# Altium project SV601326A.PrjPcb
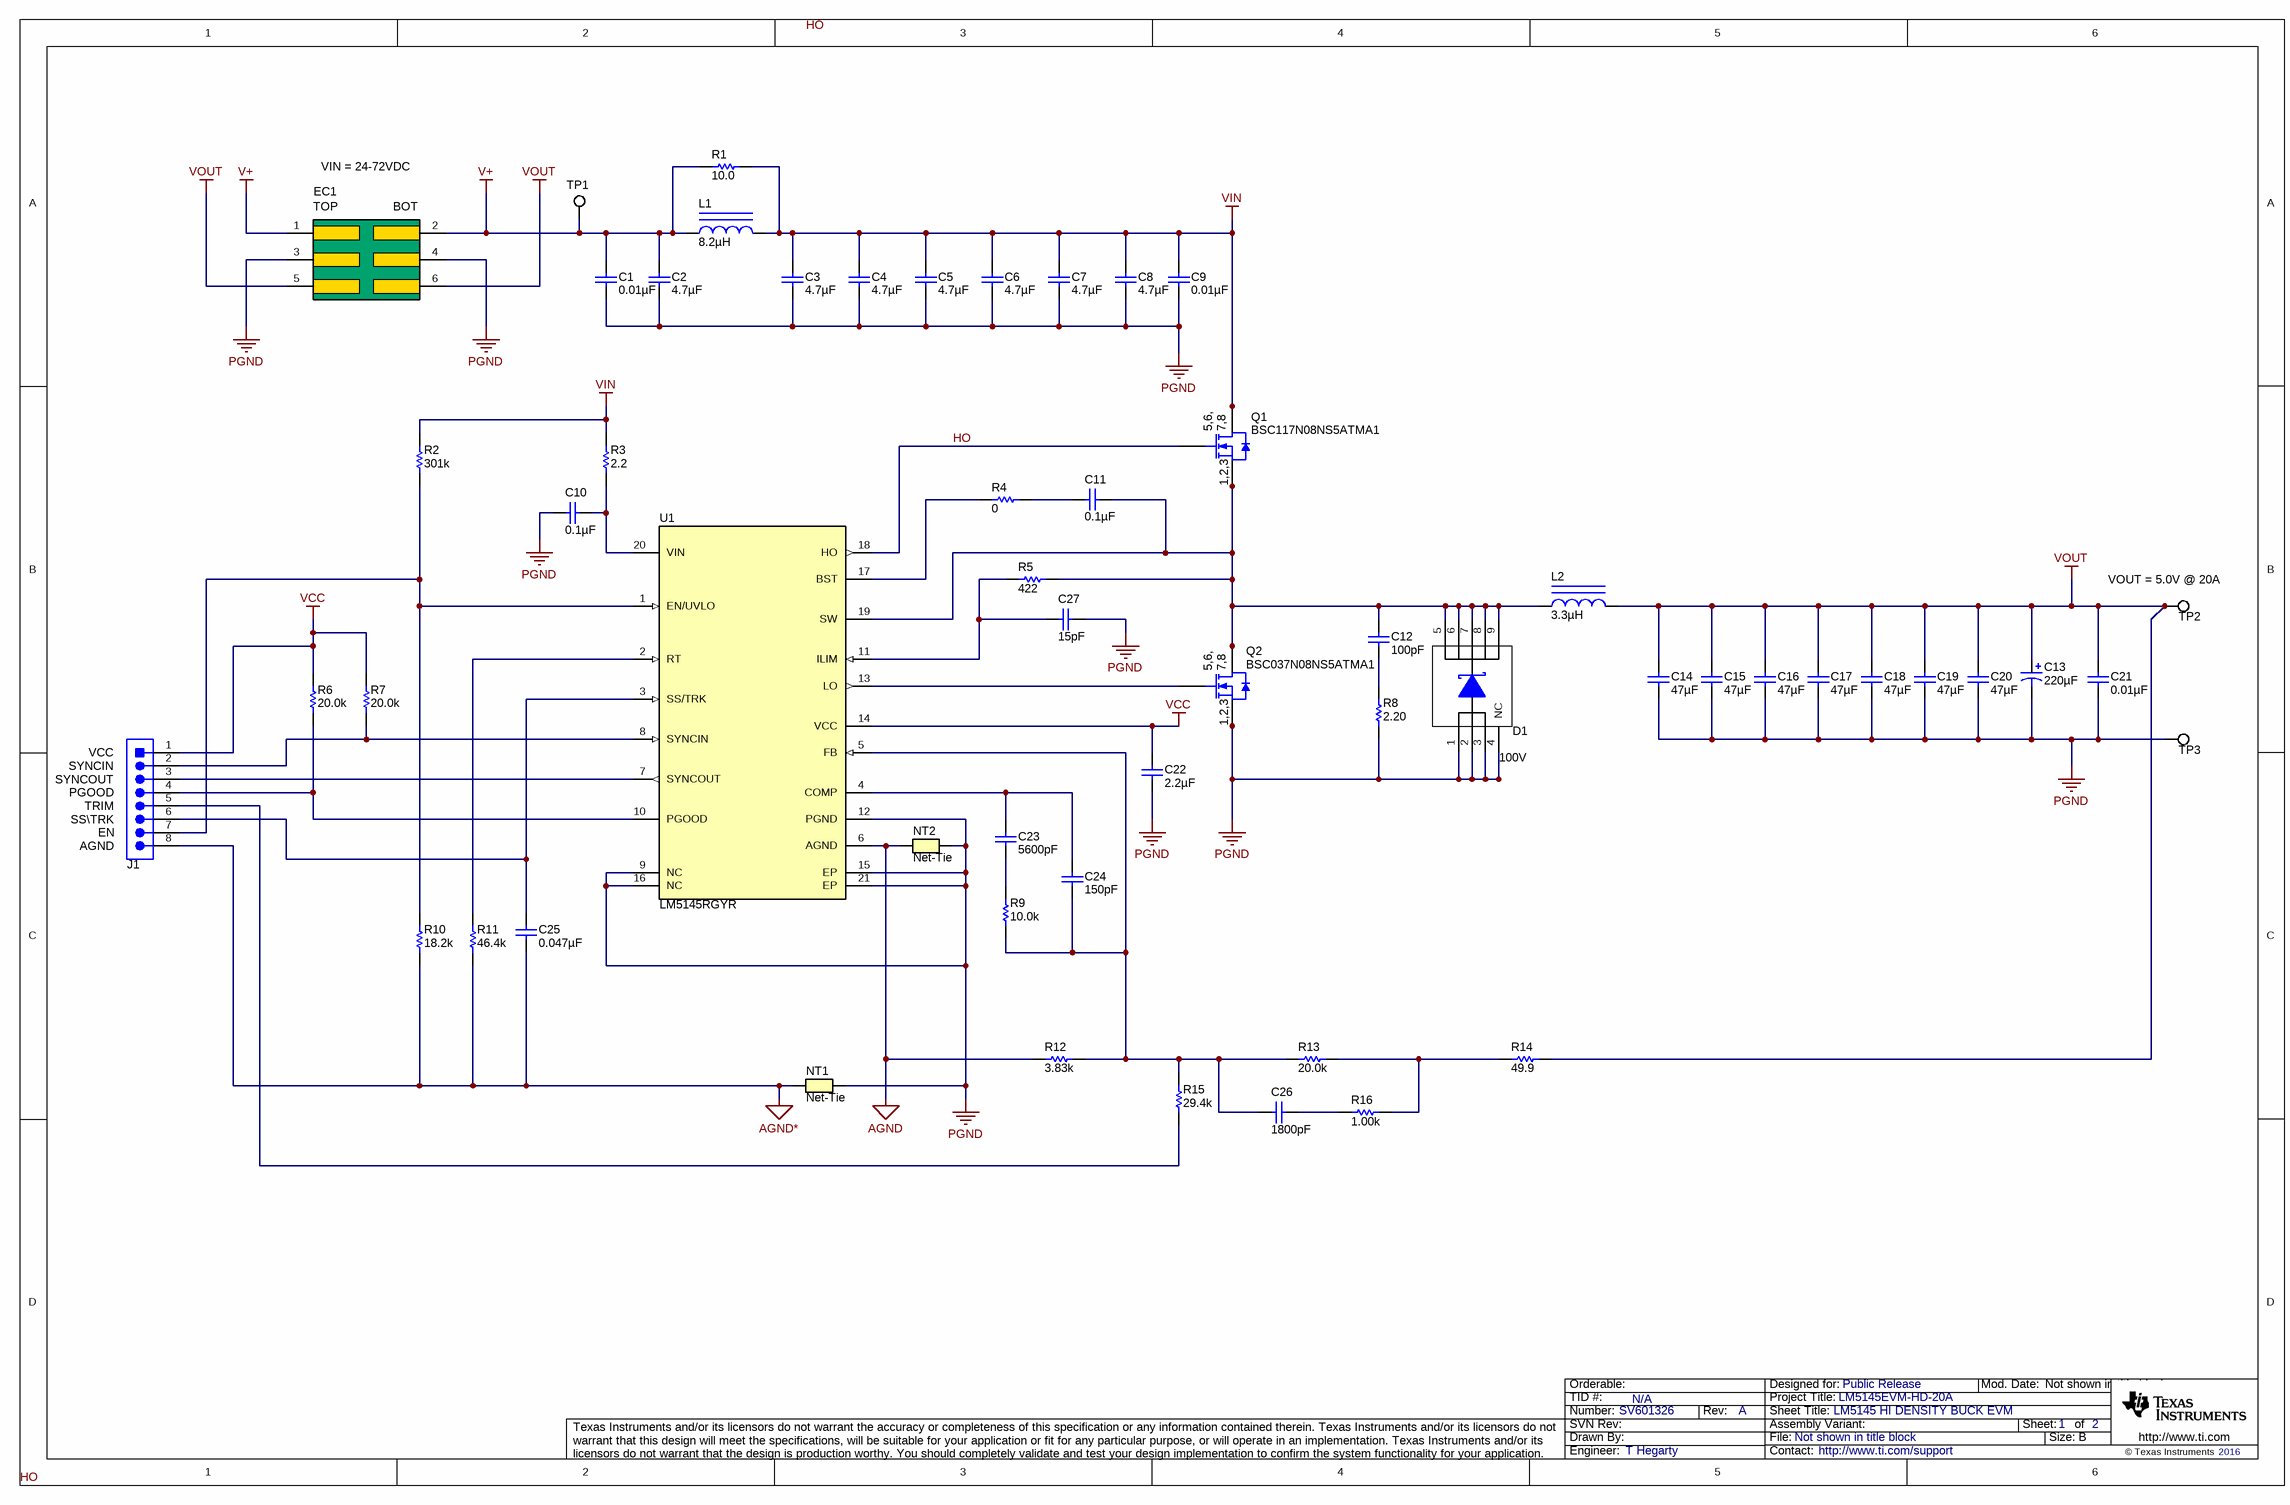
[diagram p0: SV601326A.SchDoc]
CopyrightYear: 2016; PCB_Layout: K Nielson; PCB_Rev: A; PRJ_Customer: Public Release; PRJ_Engineer: T Hegarty; PRJ_Number: SV601326; PRJ_Title: LM5145EVM-HD-20A; SCH_Rev: A; TechSupport: http://www.ti.com/support; TID: N/A
2 sheets, 64 parts. Net scope: global (net labels, ports and power ports of the same name join across sheets).
Board file: SV601326A.PcbDoc
Sheets:
  SV601326A.SchDoc
  SV601326A_HW.SchDoc

## Sheet SV601326A.SchDoc: LM5145 HI DENSITY BUCK EVM
size 431 x 279 mm; Date: Not shown in title block; ApprovedBy: Not shown in title block; CheckedBy: Not shown in title block; Author: Not shown in title block; CompanyName: Not shown in title block; Engineer: Not shown in title block; Organization: Not shown in title block; Address1: Not shown in title block; Address2: Not shown in title block; Address3: Not shown in title block; Address4: Not shown in title block; DocumentNumber: 1; Revision: Use project parameter SCH_Rev; SheetNumber: 1; SheetTotal: 2; PageSetup: Record=PageOptions¦CenterHorizontal=True¦CenterVertical=True¦PrintScale=0.62¦XCorrection=1.00¦YCorrection=1.00¦PrintKind=0¦BorderSize=5000000¦LeftOffset=0¦BottomOffset=0¦Orientation=2¦PaperLength=1000¦PaperWidth=1000¦Scale=100¦PaperSource=15¦PrintQuality=600¦MediaType=1¦DitherType=10¦PrintScaleMode=1¦PaperKind=Letter

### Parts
C1  ValueDisplayed: 0.01µF  [0603L]  (hidden comment: GRM188R72A103KA01D)
C2  ValueDisplayed: 4.7µF  [1210_220]  (hidden comment: GRM32DC72A475KE01L)
C3  ValueDisplayed: 4.7µF  [1210_220]  (hidden comment: GRM32DC72A475KE01L)
C4  ValueDisplayed: 4.7µF  [1210_220]  (hidden comment: GRM32DC72A475KE01L)
C5  ValueDisplayed: 4.7µF  [1210_220]  (hidden comment: GRM32DC72A475KE01L)
C6  ValueDisplayed: 4.7µF  [1210_220]  (hidden comment: GRM32DC72A475KE01L)
C7  ValueDisplayed: 4.7µF  [1210_220]  (hidden comment: GRM32DC72A475KE01L)
C8  ValueDisplayed: 4.7µF  [1210_220]  (hidden comment: GRM32DC72A475KE01L)
C9  ValueDisplayed: 0.01µF  [0603L]  (hidden comment: GRM188R72A103KA01D)
C10  ValueDisplayed: 0.1µF  [0603L]  (hidden comment: GRM188R72A104KA35D)
C11  ValueDisplayed: 0.1µF  [0603L]  (hidden comment: GRM188R72A104KA35D)
C12  ValueDisplayed: 100pF  [0603L]  (hidden comment: C1608C0G2A101F080AA)
C13  220µF  [7343-31]
C14  ValueDisplayed: 47µF  [1210_270]  (hidden comment: GRM32ER71A476ME15L)
C15  ValueDisplayed: 47µF  [1210_270]  (hidden comment: GRM32ER71A476ME15L)
C16  ValueDisplayed: 47µF  [1210_270]  (hidden comment: GRM32ER71A476ME15L)
C17  ValueDisplayed: 47µF  [1210_270]  (hidden comment: GRM32ER71A476ME15L)
C18  ValueDisplayed: 47µF  [1210_270]  (hidden comment: GRM32ER71A476ME15L)
C19  ValueDisplayed: 47µF  [1210_270]  (hidden comment: GRM32ER71A476ME15L)
C20  ValueDisplayed: 47µF  [1210_270]  (hidden comment: GRM32ER71A476ME15L)
C21  ValueDisplayed: 0.01µF  [0603L]  (hidden comment: GRM188R72A103KA01D)
C22  ValueDisplayed: 2.2µF  [0603L]  (hidden comment: EMK107BB7225MA-T)
C23  ValueDisplayed: 5600pF  [0603L]  (hidden comment: GRM188R71E562KA01D)
C24  ValueDisplayed: 150pF  [0603L]  (hidden comment: GRM1885C1H151JA01D)
C25  ValueDisplayed: 0.047µF  [0603L]  (hidden comment: C1608X7R1H473K080AA)
C26  ValueDisplayed: 1800pF  [0603L]  (hidden comment: GRM1885C1H182JA01D)
C27  ValueDisplayed: 15pF  [0603L]  (hidden comment: GRM1885C2A150JA01D)
D1  100V  [PowerFLAT_3_3x3_3]
EC1  EDGE_CONN_6651712-1  [TE_EDGE_CONN_6651712-1]  (value not drawn)  (no BOM)
J1  PEC08SAAN  [SULLINS_PEC08SAAN]  (value not drawn)
L1  ValueDisplayed: 8.2µH  [XAL4040]  (hidden comment: XAL4040-822MEB)
L2  ValueDisplayed: 3.3µH  [CMLS136E]  (hidden comment: CMLS136E-3R3MS)
NT1  Net-Tie  [Net-Tie_50milWide_30milLong]  (net tie, no BOM)
NT2  Net-Tie  [Net-Tie_10mil]  (net tie, no BOM)
Q1  BSC117N08NS5ATMA1  [PG-TDSON-8]
Q2  BSC037N08NS5ATMA1  [PG-TDSON-8]
R1  ValueDisplayed: 10.0  [1206L]  (hidden comment: CRCW120610R0FKEA)
R2  ValueDisplayed: 301k  [0805_HV]  (hidden comment: CRCW0805301KFKEA)
R3  ValueDisplayed: 2.2  [0603L]  (hidden comment: CRCW06032R20JNEA)
R4  ValueDisplayed: 0  [0603L]  (hidden comment: CRCW06030000Z0EA)
R5  ValueDisplayed: 422  [0603L]  (hidden comment: CRCW0603422RFKEA)
R6  ValueDisplayed: 20.0k  [0603L]  (hidden comment: CRCW060320K0FKEA)
R7  ValueDisplayed: 20.0k  [0603L]  (hidden comment: CRCW060320K0FKEA)
R8  ValueDisplayed: 2.20  [0805_HV]  (hidden comment: RC0805FR-072R2L)
R9  ValueDisplayed: 10.0k  [0603L]  (hidden comment: CRCW060310K0FKEA)
R10  ValueDisplayed: 18.2k  [0603L]  (hidden comment: CRCW060318K2FKEA)
R11  ValueDisplayed: 46.4k  [0603L]  (hidden comment: CRCW060346K4FKEA)
R12  ValueDisplayed: 3.83k  [0603L]  (hidden comment: CRCW06033K83FKEA)
R13  ValueDisplayed: 20.0k  [0603L]  (hidden comment: CRCW060320K0FKEA)
R14  ValueDisplayed: 49.9  [0603L]  (hidden comment: CRCW060349R9FKEA)
R15  ValueDisplayed: 29.4k  [0603L]  (hidden comment: CRCW060329K4FKEA)
R16  ValueDisplayed: 1.00k  [0603L]  (hidden comment: CRCW06031K00FKEA)
TP1  5015  [Testpoint_Keystone_Miniature]  (value not drawn)
TP2  5015  [Testpoint_Keystone_Miniature]  (value not drawn)
TP3  5015  [Testpoint_Keystone_Miniature]  (value not drawn)
U1  LM5145RGYR  [RGY0020B]

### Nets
AGND: NT2.2 R12.1 U1.6(AGND)
AGND*: C25.2 J1.8 NT1.1 R10.1 R11.1
PGND: C1.2 C2.2 C3.2 C4.2 C5.2 C6.2 C7.2 C8.2 C9.2 C10.2 C13.2(-) C14.2 C15.2 C16.2 C17.2 C18.2 C19.2 C20.2 C21.2 C22.2 C27.1 D1.1(A) D1.2(A) D1.3(A) D1.4(NC) EC1.3 EC1.4 NT1.2 NT2.1 Q2.1(S) Q2.2(S) Q2.3(S) R8.1 TP3.1 U1.9(NC) U1.12(PGND) U1.15(EP) U1.16(NC) U1.21(EP)
V+: C1.1 C2.1 EC1.1 EC1.2 L1.1 R1.1 TP1.1
VCC: C22.1 J1.1 R6.1 R7.1 U1.14(VCC)
VIN: C3.1 C4.1 C5.1 C6.1 C7.1 C8.1 C9.1 L1.2 Q1.5(D) Q1.6(D) Q1.7(D) Q1.8(D) Q1.9(D) R1.2 R2.2 R3.2
VOUT: C13.1(+) C14.1 C15.1 C16.1 C17.1 C18.1 C19.1 C20.1 C21.1 EC1.5 EC1.6 L2.2 R14.2 TP2.1
HO: Q1.4(G) U1.18(HO)
NetC10_1: C10.1 R3.1 U1.20(VIN)
NetC11_1: C11.1 C12.1 D1.5(K) D1.6(K) D1.7(K) D1.8(K) D1.9(K) L2.1 Q1.1(S) Q1.2(S) Q1.3(S) Q2.5(D) Q2.6(D) Q2.7(D) Q2.8(D) Q2.9(D) R5.2 U1.19(SW)
NetC11_2: C11.2 R4.2
NetC12_2: C12.2 R8.2
NetC23_1: C23.1 C24.1 U1.4(COMP)
NetC23_2: C23.2 R9.2
NetC24_2: C24.2 C26.2 R9.1 R12.2 R13.1 R15.2 U1.5(FB)
NetC25_1: C25.1 J1.6 U1.3(SS/TRK)
NetC26_1: C26.1 R16.1
NetC27_2: C27.2 R5.1 U1.11(ILIM)
NetJ1_2: J1.2 R7.2 U1.8(SYNCIN)
NetJ1_3: J1.3 U1.7(SYNCOUT)
NetJ1_4: J1.4 R6.2 U1.10(PGOOD)
NetJ1_5: J1.5 R15.1
NetJ1_7: J1.7 R2.1 R10.2 U1.1(EN/UVLO)
NetQ2_4: Q2.4(G) U1.13(LO)
NetR4_1: R4.1 U1.17(BST)
NetR11_2: R11.2 U1.2(RT)
NetR13_2: R13.2 R14.1 R16.2

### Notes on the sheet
- VIN = 24-72VDC
- (near TP2) VOUT = 5.0V @ 20A
- (near J1) SYNCOUT
- (near J1) SYNCIN
- (near J1) VCC
- (near J1) PGOOD
- (near J1) SS\TRK
- (near J1) AGND
- (near J1) TRIM
- (near J1) EN
- Labels drawn without touching a wire or pin: HO

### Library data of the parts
C1 C9 C21 = GRM188R72A103KA01D: CAP, CERM, 0.01 µF, 100 V, +/- 10%, X7R, 0603; Manufacturer: MuRata; Polarized: N; CompType: Capacitor; Value: 0.01uF; U/M: EA; Cap_F: 0.00000001; Tolerance_%: 10; Value1: Unknown; VDC_V: 100; Value2: 100V; TaMin_C: -55; TaMax_C: 125; Cap_Case: 0603; AEC Category: Q200; SizeArea_mm2: 1.28; SizeAreaWB_mm2: 4.68; SizeX_mm: 1.6; SizeY_mm: 0.8; SizeZ_mm: 1
C2-C8 = GRM32DC72A475KE01L: CAP, CERM, 4.7 µF, 100 V, +/- 10%, X7S, 1210; Manufacturer: MuRata; Polarized: N; CompType: Capacitor; Value: 4.7uF; U/M: EA; Cap_F: 0.0000047; Tolerance_%: 10; Value1: Unknown; VDC_V: 100; Value2: 100V; TaMin_C: -55; TaMax_C: 125; Cap_Case: 1210; AEC Category: Q200; SizeArea_mm2: 8; SizeAreaWB_mm2: 14.7; SizeX_mm: 3.2; SizeY_mm: 2.5; SizeZ_mm: 2.2
C10 C11 = GRM188R72A104KA35D: CAP, CERM, 0.1 µF, 100 V, +/- 10%, X7R, 0603; Manufacturer: MuRata; Polarized: N; CompType: Capacitor; Value: 0.1uF; U/M: EA; Cap_F: 0.0000001; Tolerance_%: 10; Value1: Unknown; VDC_V: 100; Value2: 100V; TaMin_C: -55; TaMax_C: 125; Cap_Case: 0603; AEC Category: Q200
C12 = C1608C0G2A101F080AA: CAP, CERM, 100 pF, 100 V, +/- 1%, C0G/NP0, 0603; Manufacturer: TDK; Polarized: N; CompType: Capacitor; Value: 100pF; U/M: EA; Cap_F: 0.0000000001; Tolerance_%: 1; Value1: Unknown; VDC_V: 100; Value2: 100V; TaMin_C: -55; TaMax_C: 125; Cap_Case: 0603; AEC Category: Q200
C13 = ECASD60J227M010K00: CAP ALUM POLY 220UF 20% 6.3V SMD; Manufacturer: Murata Electronics North America; CompType: Used in some BOM reports.  Useful for finding later.; SymbolVersion: use current date i.e. 2008-05-20; U/M: EA, IN, or GM; ESR_Ohm: 10 mOhm; SymbolCreator: Use a-id; Lifetime @ Temp.: 1000 Hrs @ 105°C; Type: Polymer; Ripple Current: 3A
C14-C20 = GRM32ER71A476ME15L: CAP, CERM, 47 µF, 10 V, +/- 20%, X7R, 1210; Manufacturer: MuRata; Polarized: N; CompType: Capacitor; Value: 47uF; U/M: EA; Cap_F: 0.000047; Tolerance_%: 20; Value1: Unknown; VDC_V: 10; Value2: 10V; TaMin_C: -55; TaMax_C: 125; Cap_Case: 1210; AEC Category: Q200; SizeArea_mm2: 8; SizeAreaWB_mm2: 14.7; SizeX_mm: 3.2; SizeY_mm: 2.5; SizeZ_mm: 2.7
C22 = EMK107BB7225MA-T: CAP, CERM, 2.2 µF, 16 V, +/- 10%, X7R, 0603; Manufacturer: Taiyo Yuden; Polarized: N; CompType: Capacitor; Value: 2.2uF; U/M: EA; Cap_F: 0.0000022; Tolerance_%: 10; Value1: Unknown; VDC_V: 16; Value2: 16V; TaMin_C: -55; TaMax_C: 125; Cap_Case: 0603; AEC Category: Q200; SizeArea_mm2: 1.28; SizeAreaWB_mm2: 4.68; SizeX_mm: 1.6; SizeY_mm: 0.8; SizeZ_mm: 1
C23 = GRM188R71E562KA01D: CAP, CERM, 5600 pF, 25 V, +/- 10%, X7R, 0603; Manufacturer: MuRata; Polarized: N; CompType: Capacitor; Value: 5600pF; U/M: EA; Cap_F: 0.0000000056; Tolerance_%: 10; Value1: Unknown; VDC_V: 25; Value2: 25V; TaMin_C: -55; TaMax_C: 125; Cap_Case: 0603; AEC Category: Q200; SizeArea_mm2: 1.28; SizeAreaWB_mm2: 4.68; SizeX_mm: 1.6; SizeY_mm: 0.8; SizeZ_mm: 1
C24 = GRM1885C1H151JA01D: CAP, CERM, 150 pF, 50 V, +/- 5%, C0G/NP0, 0603; Manufacturer: MuRata; Polarized: N; CompType: Capacitor; Value: 150pF; U/M: EA; Cap_F: 0.00000000015; Tolerance_%: 5; Value1: Unknown; VDC_V: 50; Value2: 50V; TaMin_C: -55; TaMax_C: 125; Cap_Case: 0603; AEC Category: Q200; SizeArea_mm2: 1.28; SizeAreaWB_mm2: 4.68; SizeX_mm: 1.6; SizeY_mm: 0.8; SizeZ_mm: 1
C25 = C1608X7R1H473K080AA: CAP, CERM, 0.047 µF, 50 V, +/- 10%, X7R, 0603; Manufacturer: TDK; Polarized: N; CompType: Capacitor; Value: 0.047uF; U/M: EA; Cap_F: 0.000000047; Tolerance_%: 10; ESR_ohm: 0.049007; Value1: 0.049007 ohm; VDC_V: 50; Value2: 50V; IRMS_A: 0.767528; TaMin_C: -55; TaMax_C: 125; Cap_Case: 0603; AEC Category: Q200
C26 = GRM1885C1H182JA01D: CAP, CERM, 1800 pF, 50 V, +/- 5%, C0G/NP0, 0603; Manufacturer: MuRata; Polarized: N; CompType: Capacitor; Value: 1800pF; U/M: EA; Cap_F: 0.0000000018; Tolerance_%: 5; Value1: Unknown; VDC_V: 50; Value2: 50V; TaMin_C: -55; TaMax_C: 125; Cap_Case: 0603; AEC Category: Q200; SizeArea_mm2: 1.28; SizeAreaWB_mm2: 4.68; SizeX_mm: 1.6; SizeY_mm: 0.8; SizeZ_mm: 1
C27 = GRM1885C2A150JA01D: CAP, CERM, 15 pF, 100 V, +/- 5%, C0G/NP0, 0603; Manufacturer: MuRata; Polarized: N; CompType: Capacitor; Value: 15pF; U/M: EA; Cap_F: 0.000000000015; Tolerance_%: 5; Value1: Unknown; VDC_V: 100; Value2: 100V; TaMin_C: -55; TaMax_C: 125; Cap_Case: 0603; SizeArea_mm2: 1.28; SizeAreaWB_mm2: 4.68; SizeX_mm: 1.6; SizeY_mm: 0.8; SizeZ_mm: 1; AEC Category: Q200
D1 = STPS6M100DEE-TR: Diode, Schottky, 100 V, 6 A, 8-PowerTDFN; Manufacturer: STMicroelectronics; U/M: EA; Vf_V: 0.64; Value1: 6A; Value2: 0.64V; Io_A: 6; Vr_V: 100; TJmax_C: 150; RJC_CperW: 4; AEC Category: Q101; AEC Qualified: N; SymbolCreator: Altium
EC1 = EDGE_CONN_6651712-1: Card Edge Footprint, 3x2; Manufacturer: TE Connectivity; SymbolCreator: Altium
J1 = PEC08SAAN: Header, 100mil, 8x1, Tin, TH; Manufacturer: Sullins Connector Solutions; SymbolCreator: a0411947; Pitch_mm: 2.54; Gender: Male; Shrouded: N; Row_Count: 1; Current_A: 3; Voltage_V: 1800; Cert_UL: Y
L1 = XAL4040-822MEB: Inductor, Shielded, Composite, 8.2 µH, 3.4 A, 0.0608 ohm, SMD; Manufacturer: Coilcraft; Value: 8.2uH; Ind_H: 8.2E-6; Imax_A: 3.4; Irms: 3.4A @ 40C rise; Isat: 4A @ 30% inductance drop; DCR_ohm: 0.0608; Value2: 3.4A; AEC Category: Q200; SizeAreaWB_mm2: 25; SizeArea_mm2: 16; SizeX_mm: 4; SizeZ_mm: 4.1
L2 = CMLS136E-3R3MS: Inductor, 3.3 µH, 20 A, 0.0044 ohm, SMD; Manufacturer: Cyntec; Value: 3.3uH; Ind_H: 3.3E-6; Imax_A: 20; Irms: 20A @ 40C rise; Isat: 40A @ 30% inductance drop; DCR_ohm: 0.0044; Value2: 20A; AEC Category: Q200; AEC Qualified: N; SizeAreaWB_mm2: 225.57; SizeArea_mm2: 169.47; SizeX_mm: 13.45; SizeY_mm: 12.6; SizeZ_mm: 6.5
NT1 NT2 = Net-Tie: Single point connection between nets.; SymbolCreator: codlsc
Q1 = BSC117N08NS5ATMA1: MOSFET, N-CH, 80 V, 49 A, PG-TDSON-8; Manufacturer: Infineon Technologies; Alternate Manufacturer: None; U/M: EA; ChType: N; Value: 80V; VdsMax_V: 80; Value1: ? ohm; Value2: 15 nC; QgTyp_nC: 15; Vgs_V: 20; IdsMax_A: 49; AEC Category: Q101
Q2 = BSC037N08NS5ATMA1: MOSFET N-CH 80V 100A 8TDSON; Manufacturer: Infineon Technologies; SymbolVersion: use current date i.e. 2008-05-20; SymbolCreator: Use a-id; CompType: Used in some BOM reports.  Useful for finding later.; U/M: EA, IN, or GM; Gate Charge (Qg) @ Vgs: 58nC @ 10V; FET Type: MOSFET N-Channel, Metal Oxide; FET Feature: Standard; Vgs(th) (Max) @ Id: 3.8V @ 72µA; Input Capacitance (Ciss) @ Vds: 4200pF @ 40V; Rds On (Max) @ Id, Vgs: 3.7 mOhm @ 50A, 10V; Power - Max: 2.5W; Current - Continuous Drain (Id) @ 25°C: 100A (Tc)
R1 = CRCW120610R0FKEA: RES, 10.0, 1%, 0.25 W, 1206; Manufacturer: Vishay-Dale; CompType: Resistor; Value: 10.0; Res_ohm: 10; Value_Code: 10R0; Tolerance_%: 1; Power_W: 0.25; Value2: 0.25W; VDC_V: 200; TempCo: 100 ppm/C; SizeArea_mm2: 5.12; SizeX_mm: 3.2; SizeY_mm: 1.6; SizeZ_mm: 1.35; EIA_Code: E96; U/M: EA; AEC Category: Q200
R2 = CRCW0805301KFKEA: RES, 301 k, 1%, 0.125 W, 0805; Manufacturer: Vishay-Dale; CompType: Resistor; Value: 301k; Res_ohm: 301000; Tolerance_%: 1; Power_W: 0.125; Value2: 0.125W; VDC_V: 150; TempCo: 100 ppm/C; EIA_Code: E96; U/M: EA; AEC Category: Q200; SizeArea_mm2: 2.5; SizeX_mm: 2; SizeY_mm: 1.25; SizeZ_mm: 1.45
R3 = CRCW06032R20JNEA: RES, 2.2, 5%, 0.1 W, 0603; Manufacturer: Vishay-Dale; CompType: Resistor; Value: 2.2; Value_Code: 2R20; Tolerance_%: 5; Power_W: 0.1; Value2: 0.1W; VDC_V: 75; TempCo: 200 ppm/C; EIA_Code: E24; U/M: EA; AEC Category: Q200
R4 = CRCW06030000Z0EA: RES, 0, 5%, 0.1 W, 0603; Manufacturer: Vishay-Dale; CompType: Resistor; Value: 0; Value_Code: 0000; Tolerance_%: 5; Power_W: 0.1; Value2: 0.1W; VDC_V: 75; TempCo: 200 ppm/C; EIA_Code: E24; U/M: EA; AEC Category: Q200
R5 = CRCW0603422RFKEA: RES, 422, 1%, 0.1 W, 0603; Manufacturer: Vishay-Dale; CompType: Resistor; Value: 422; Value_Code: 422R; Tolerance_%: 1; Power_W: 0.1; Value2: 0.1W; VDC_V: 75; TempCo: 100 ppm/C; EIA_Code: E96; U/M: EA; AEC Category: Q200; SizeArea_mm2: 1.28; SizeX_mm: 1.6; SizeY_mm: 0.8
R6 R7 = CRCW060320K0FKEA: RES, 20.0 k, 1%, 0.1 W, 0603; Manufacturer: Vishay-Dale; CompType: Resistor; Value: 20.0k; Res_ohm: 20000; Value_Code: 20k0; Tolerance_%: 1; Power_W: 0.1; Value2: 0.1W; VDC_V: 75; TempCo: 100 ppm/C; EIA_Code: E96; U/M: EA; AEC Category: Q200
R8 = RC0805FR-072R2L: RES, 2.20, 1%, 0.125 W, 0805; Manufacturer: Yageo America; CompType: Resistor; Value: 2.20; Res_ohm: 2.2; Value_Code: 2R20; Tolerance_%: 1; Power_W: 0.125; Value2: 0.125W; VDC_V: 150; TempCo: 200 ppm/C; U/M: EA; AEC Category: Q200
R9 = CRCW060310K0FKEA: RES, 10.0 k, 1%, 0.1 W, 0603; Manufacturer: Vishay-Dale; CompType: Resistor; Value: 10.0k; Res_ohm: 10000; Value_Code: 10k0; Tolerance_%: 1; Power_W: 0.1; Value2: 0.1W; VDC_V: 75; TempCo: 100 ppm/C; EIA_Code: E96; U/M: EA; AEC Category: Q200; SizeArea_mm2: 1.28; SizeX_mm: 1.6; SizeY_mm: 0.8
R10 = CRCW060318K2FKEA: RES, 18.2 k, 1%, 0.1 W, 0603; Manufacturer: Vishay-Dale; CompType: Resistor; Value: 18.2k; Res_ohm: 18200; Value_Code: 18k2; Tolerance_%: 1; Power_W: 0.1; Value2: 0.1W; VDC_V: 75; TempCo: 100 ppm/C; EIA_Code: E96; U/M: EA; AEC Category: Q200; SizeArea_mm2: 1.28; SizeX_mm: 1.6; SizeY_mm: 0.8
R11 = CRCW060346K4FKEA: RES, 46.4 k, 1%, 0.1 W, 0603; Manufacturer: Vishay-Dale; CompType: Resistor; Value: 46.4k; Res_ohm: 46400; Value_Code: 46k4; Tolerance_%: 1; Power_W: 0.1; Value2: 0.1W; VDC_V: 75; TempCo: 100 ppm/C; EIA_Code: E96; U/M: EA; AEC Category: Q200; SizeArea_mm2: 1.28; SizeX_mm: 1.6; SizeY_mm: 0.8
R12 = CRCW06033K83FKEA: RES, 3.83 k, 1%, 0.1 W, 0603; Manufacturer: Vishay-Dale; CompType: Resistor; Value: 3.83k; Res_ohm: 3830; Value_Code: 3k83; Tolerance_%: 1; Power_W: 0.1; Value2: 0.1W; VDC_V: 75; TempCo: 100 ppm/C; EIA_Code: E96; U/M: EA; AEC Category: Q200; SizeArea_mm2: 1.28; SizeX_mm: 1.6; SizeY_mm: 0.8
R13 = CRCW060320K0FKEA: RES, 20.0 k, 1%, 0.1 W, 0603; Manufacturer: Vishay-Dale; CompType: Resistor; Value: 20.0k; Res_ohm: 20000; Value_Code: 20k0; Tolerance_%: 1; Power_W: 0.1; Value2: 0.1W; VDC_V: 75; TempCo: 100 ppm/C; EIA_Code: E96; U/M: EA; AEC Category: Q200; SizeArea_mm2: 1.28; SizeX_mm: 1.6; SizeY_mm: 0.8
R14 = CRCW060349R9FKEA: RES, 49.9, 1%, 0.1 W, 0603; Manufacturer: Vishay-Dale; CompType: Resistor; Value: 49.9; Value_Code: 49R9; Tolerance_%: 1; Power_W: 0.1; Value2: 0.1W; VDC_V: 75; TempCo: 100 ppm/C; EIA_Code: E96; U/M: EA; AEC Category: Q200
R15 = CRCW060329K4FKEA: RES, 29.4 k, 1%, 0.1 W, 0603; Manufacturer: Vishay-Dale; CompType: Resistor; Value: 29.4k; Res_ohm: 29400; Value_Code: 29k4; Tolerance_%: 1; Power_W: 0.1; Value2: 0.1W; VDC_V: 75; TempCo: 100 ppm/C; EIA_Code: E96; U/M: EA; AEC Category: Q200; SizeArea_mm2: 1.28; SizeX_mm: 1.6; SizeY_mm: 0.8
R16 = CRCW06031K00FKEA: RES, 1.00 k, 1%, 0.1 W, 0603; Manufacturer: Vishay-Dale; CompType: Resistor; Value: 1.00k; Res_ohm: 1000; Value_Code: 1k00; Tolerance_%: 1; Power_W: 0.1; Value2: 0.1W; VDC_V: 75; TempCo: 100 ppm/C; EIA_Code: E96; U/M: EA; AEC Category: Q200; SizeArea_mm2: 1.28; SizeX_mm: 1.6; SizeY_mm: 0.8
TP1-TP3 = 5015: Test Point, Miniature, SMT; Manufacturer: Keystone; CompType: Test Point Loop
U1 = LM5145RGYR: Wide Input Range Synchronous Buck Controller, RGY0020B; Alternate PartNumber: LM5145RGYT; Manufacturer: Texas Instruments; SymbolCreator: Altium; CompType: IC; U/M: EA

## Sheet SV601326A_HW.SchDoc: LM5145EVM Hardware
size 431 x 279 mm; Date: Not shown in title block; ApprovedBy: Not shown in title block; CheckedBy: Not shown in title block; Author: Not shown in title block; CompanyName: Not shown in title block; Engineer: Not shown in title block; Organization: Not shown in title block; Address1: Not shown in title block; Address2: Not shown in title block; Address3: Not shown in title block; Address4: Not shown in title block; DocumentNumber: 2; Revision: Use project parameter SCH_Rev; SheetNumber: 2; SheetTotal: 2; PageSetup: Record=PageOptions¦CenterHorizontal=True¦CenterVertical=True¦PrintScale=1.00¦XCorrection=1.00¦YCorrection=1.00¦PrintKind=0¦BorderSize=5000000¦LeftOffset=0¦BottomOffset=0¦Orientation=2¦PaperLength=1000¦PaperWidth=1000¦Scale=100¦PaperSource=15¦PrintQuality=600¦MediaType=1¦DitherType=10¦PaperKind=Letter¦PrintScaleMode=1
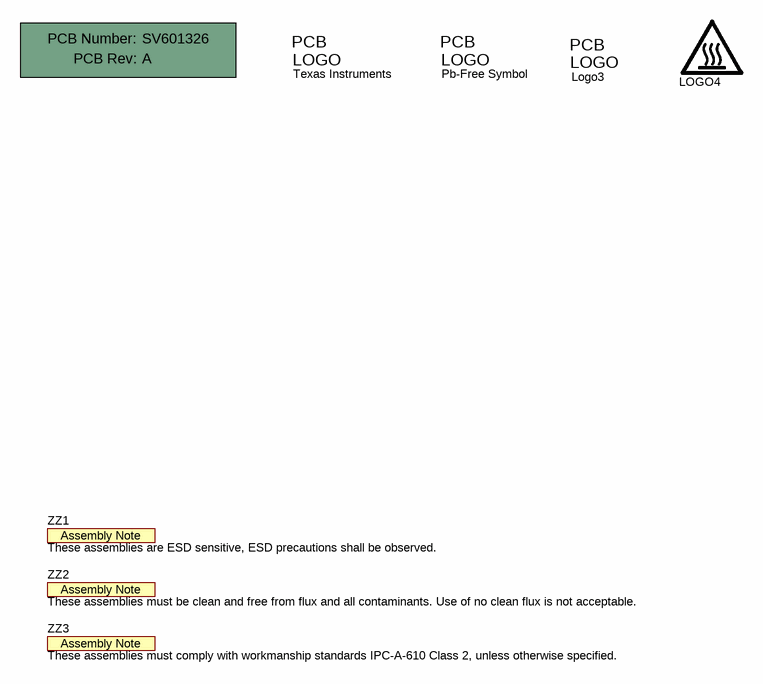
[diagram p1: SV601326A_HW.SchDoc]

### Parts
!PCB1  Printed Circuit Board  (value not drawn)  (mechanical)
Logo1  Texas Instruments  [TI_Stacked_Overlay_Small]  (no BOM)
Logo2  Pb-Free Symbol  [Pb-Free_Overlay_Small]  (no BOM)
Logo3  FCC disclaimer  [FCC_disclaimer]  (value not drawn)  (no BOM)
LOGO4  CAUTION HOT SURFACE  [IEC_HotSurface_Small]  (value not drawn)  (no BOM)
ZZ1  These assemblies are ESD sensitive, ESD precautions shall be observed.  [AssemblyNote]  (no BOM)
ZZ2  These assemblies must be clean and free from flux and all contaminants. Use of no clean flux is not acceptable.  [AssemblyNote]  (no BOM)
ZZ3  These assemblies must comply with workmanship standards IPC-A-610 Class 2, unless otherwise specified.  [AssemblyNote]  (no BOM)

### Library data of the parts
!PCB1 = PCB: Manufacturer: Any; PartNumber: SV601326; SymbolCreator: a0412235
Logo1 = TI_Logo: Texas Instrument Corporate Signature; SymbolCreator: codlsc
Logo2 = Pb-Free: SymbolCreator: a0412235
Logo3 = FCC_disclaimer: SymbolCreator: a0412235
LOGO4 = IEC_HotSurface: IEC 61010-1 Hot Surface Warning; SymbolCreator: a0412235
ZZ1-ZZ3 = AssemblyNote: SymbolCreator: codlsc

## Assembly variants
001: not fitted C12 J1 LBL1 R8
002: not fitted C12 C13 R8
